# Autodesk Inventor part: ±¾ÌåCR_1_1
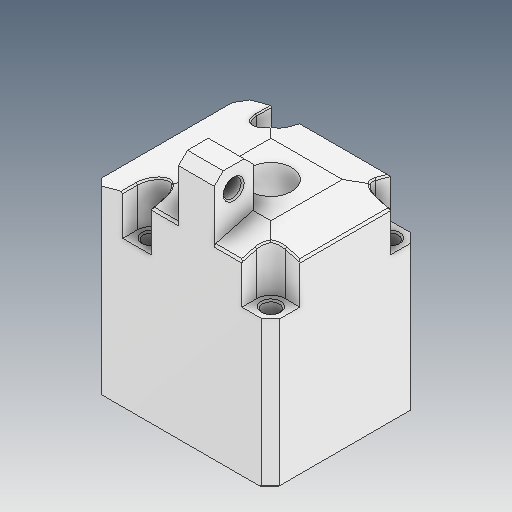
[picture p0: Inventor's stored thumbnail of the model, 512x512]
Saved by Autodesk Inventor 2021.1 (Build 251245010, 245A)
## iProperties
Created: 2021-05
Part Number: ±¾ÌåCR_1_1
Material: Ogólny
Document SubType Name: Modeling
Designer: user
Density: 1 g/cm^3
Appearance: Domyślna
Author: user
Revision Number: ÈÎºÎ
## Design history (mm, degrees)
feature "ÊäÈë1"
feature "ÊäÈë2"
node "Bryła1"
node "Bryła2"
